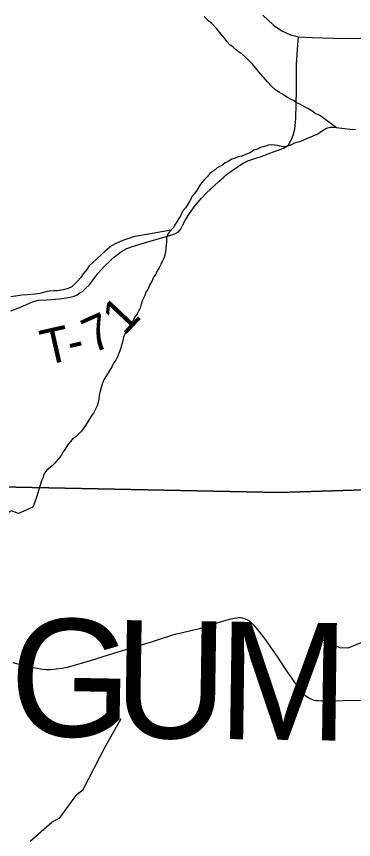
# Model space of a CAD drawing. Extents: x 0 to 34, y 0 to 22.
# Drawn here: x 27.33 to 27.873, y 17.319 to 18.646 of the extents above; entities that cross this region are included whole.
import ezdxf

# ---------------------------------------------------------------- set-up
doc = ezdxf.new("R2010")
doc.units = 0
for name, color, linetype in [('GM_X_Adjacent_County', 7, 'Continuous'), ('GM_X_Adjacent_County_Text', 7, 'Continuous'), ('GM_X_County', 7, 'Continuous'), ('GM_X_County_Road', 7, 'Continuous'), ('GM_X_Minor_River', 7, 'Continuous'), ('GM_X_Township', 7, 'Continuous'), ('GM_X_Township_Road', 7, 'Continuous'), ('GM_X_Township_Road_Text', 7, 'Continuous')]:
    doc.layers.add(name, color=color, linetype=linetype)

msp = doc.modelspace()

# ---------------------------------------------------------------- linework, layer by layer
at = {"layer": 'GM_X_Adjacent_County'}
for points in [[(29.1279, 17.8574), (28.6324, 17.8677), (28.1264, 17.8728), (27.8903, 17.8826), (27.7531, 17.8783), (27.1422, 17.8906), (26.9072, 17.9017), (26.4988, 17.9198), (26.3979, 17.9244), (26.2521, 17.9299)], [(26.2521, 17.9299), (26.3979, 17.9244), (26.4988, 17.9198), (26.9072, 17.9017), (27.1422, 17.8906), (27.7531, 17.8783), (27.8903, 17.8826), (28.1264, 17.8728), (28.6324, 17.8677), (29.1279, 17.8574)]]:
    msp.add_lwpolyline(points, dxfattribs=at)
at = {"layer": 'GM_X_County'}
for points in [[(26.2521, 17.9299), (26.3979, 17.9244), (26.4988, 17.9198), (26.9072, 17.9017), (27.1422, 17.8906), (27.7531, 17.8783), (27.8903, 17.8826), (28.1264, 17.8728), (28.6324, 17.8677), (29.1279, 17.8574)], [(29.1279, 17.8574), (28.6324, 17.8677), (28.1264, 17.8728), (27.8903, 17.8826), (27.7531, 17.8783), (27.1422, 17.8906), (26.9072, 17.9017), (26.4988, 17.9198), (26.3979, 17.9244), (26.2521, 17.9299)]]:
    msp.add_lwpolyline(points, dxfattribs=at)
at = {"layer": 'GM_X_County_Road'}
for points in [[(27.7267, 18.6482), (27.7441, 18.6319), (27.7571, 18.6229), (27.7713, 18.6162), (27.7839, 18.613)], [(27.7839, 18.613), (27.806, 18.6118), (27.8403, 18.6107), (27.8718, 18.6103), (27.8963, 18.6115)]]:
    msp.add_lwpolyline(points, dxfattribs=at)
at = {"layer": 'GM_X_Minor_River'}
for points in [[(27.8456, 18.4663), (27.82, 18.4853), (27.8163, 18.4872), (27.8109, 18.4895), (27.8071, 18.4925), (27.7992, 18.4978), (27.7912, 18.5019), (27.7855, 18.5053), (27.7817, 18.5068), (27.776, 18.5102), (27.7722, 18.5121), (27.7662, 18.5155), (27.7574, 18.5212), (27.7536, 18.5235), (27.7479, 18.5273), (27.7411, 18.5329), (27.7335, 18.5413), (27.7202, 18.5568), (27.7103, 18.5689), (27.7046, 18.5742), (27.6993, 18.5799), (27.6928, 18.5856), (27.6875, 18.589), (27.6837, 18.592), (27.6791, 18.5965), (27.6734, 18.6003), (27.6689, 18.6056), (27.6655, 18.6102), (27.659, 18.6177), (27.6525, 18.6261), (27.6445, 18.6344), (27.6396, 18.6382), (27.6324, 18.6461)], [(27.8758, 18.463), (27.8675, 18.4638), (27.8584, 18.4645), (27.8497, 18.466), (27.8406, 18.4668), (27.8349, 18.4667), (27.8292, 18.4652), (27.8228, 18.4614), (27.8152, 18.4561), (27.811, 18.4546), (27.8023, 18.4507), (27.7982, 18.4492), (27.7891, 18.445), (27.7777, 18.4416), (27.7713, 18.4382), (27.7634, 18.4355), (27.7592, 18.4359), (27.7543, 18.4366), (27.7505, 18.4377), (27.7455, 18.4385), (27.7399, 18.4388), (27.7357, 18.4385), (27.7293, 18.4362), (27.7228, 18.4346), (27.7183, 18.432), (27.7122, 18.4301), (27.7062, 18.4263), (27.7013, 18.4243), (27.6929, 18.4209), (27.6869, 18.4194), (27.6812, 18.4167), (27.6766, 18.4156), (27.671, 18.4121), (27.6661, 18.4099), (27.6615, 18.4061), (27.6532, 18.4019), (27.6479, 18.3973), (27.6419, 18.3939), (27.6381, 18.3882), (27.632, 18.3825), (27.6286, 18.3783), (27.6249, 18.3726), (27.6207, 18.3665), (27.6162, 18.3593), (27.6124, 18.3555), (27.6105, 18.3513), (27.6083, 18.3475), (27.6022, 18.3376), (27.5977, 18.3327), (27.5958, 18.3285), (27.5939, 18.3247), (27.5913, 18.3202), (27.5883, 18.3148), (27.5856, 18.3107), (27.583, 18.3057), (27.5758, 18.2981), (27.5728, 18.2932), (27.5717, 18.289), (27.5713, 18.2833), (27.571, 18.2765), (27.5706, 18.2727), (27.5699, 18.2666), (27.5676, 18.2575), (27.5646, 18.2511), (27.5623, 18.2461), (27.5593, 18.2397), (27.5563, 18.2359), (27.5541, 18.2302), (27.5507, 18.2256), (27.548, 18.2184), (27.5446, 18.2135)], [(27.5789, 18.3014), (27.5179, 18.2904), (27.5107, 18.2881), (27.5054, 18.2862), (27.4982, 18.2835), (27.4899, 18.2797), (27.4831, 18.2759), (27.4725, 18.2675), (27.4668, 18.2622), (27.46, 18.2558), (27.4517, 18.2482), (27.4468, 18.2436), (27.443, 18.2379), (27.4373, 18.231), (27.4332, 18.2253), (27.4283, 18.2189), (27.4245, 18.2151), (27.4188, 18.2098), (27.4128, 18.2071), (27.4052, 18.2052), (27.3957, 18.2036), (27.3901, 18.2036), (27.3829, 18.2029), (27.3791, 18.2025), (27.3749, 18.2013), (27.3673, 18.1994), (27.3601, 18.1979), (27.3473, 18.1971), (27.3386, 18.1963), (27.3317, 18.1955), (27.3208, 18.194)], [(27.5446, 18.2135), (27.5412, 18.2055), (27.5382, 18.2013), (27.5363, 18.196), (27.533, 18.1884), (27.5307, 18.1823), (27.5288, 18.1755), (27.5266, 18.1705), (27.5243, 18.1667), (27.5205, 18.1618), (27.5171, 18.1542), (27.5111, 18.1455), (27.5062, 18.1367), (27.5024, 18.1288), (27.4998, 18.1185), (27.4961, 18.1067), (27.4927, 18.0972), (27.4897, 18.0915), (27.4863, 18.087), (27.4833, 18.0809), (27.4791, 18.0741), (27.475, 18.0669), (27.4708, 18.0612), (27.4686, 18.0547), (27.4663, 18.0479), (27.4641, 18.0395), (27.4629, 18.0346), (27.4622, 18.0289), (27.4607, 18.022), (27.4596, 18.0183), (27.4577, 18.0137), (27.4539, 18.0065), (27.4501, 18.0012), (27.4468, 17.9962), (27.4437, 17.9909), (27.4392, 17.9841), (27.4343, 17.9772), (27.4264, 17.9692), (27.4196, 17.9639), (27.4135, 17.9567), (27.4075, 17.9476), (27.4049, 17.9438), (27.4022, 17.9388), (27.3916, 17.9255), (27.3871, 17.9213), (27.3788, 17.9145), (27.375, 17.9096), (27.3735, 17.9058), (27.372, 17.9016), (27.3701, 17.897), (27.365, 17.8814)], [(27.365, 17.8814), (27.3615, 17.8687), (27.3563, 17.8549), (27.3329, 17.8446), (27.3218, 17.8486), (27.314, 17.8445), (27.2886, 17.8365), (27.2621, 17.8368), (27.2489, 17.8269), (27.2403, 17.8151), (27.2119, 17.8104), (27.1896, 17.8046), (27.1772, 17.794)], [(28.1101, 17.8688), (28.1036, 17.8534), (28.073, 17.8298), (28.0477, 17.8088), (27.9937, 17.7753), (27.9718, 17.7562), (27.9605, 17.7437), (27.9441, 17.6875), (27.9382, 17.6616), (27.931, 17.6495), (27.9201, 17.6419), (27.8989, 17.6418), (27.8634, 17.6276), (27.8505, 17.6279), (27.8187, 17.643)], [(27.3518, 17.3162), (27.3865, 17.3467), (27.3998, 17.3536), (27.4268, 17.3916), (27.4374, 17.3996), (27.4648, 17.4528), (27.4716, 17.4661), (27.4982, 17.514)]]:
    msp.add_lwpolyline(points, dxfattribs=at)
at = {"layer": 'GM_X_Township'}
for points in [[(30.8167, 17.8174), (30.1304, 17.8301), (29.8296, 17.8449), (29.1279, 17.8574), (28.6324, 17.8677), (28.1264, 17.8728), (27.8903, 17.8826), (27.7531, 17.8783), (27.1422, 17.8906), (26.9072, 17.9017), (26.4988, 17.9198), (26.3979, 17.9244), (26.2521, 17.9299), (26.228, 17.2045)], [(26.2521, 17.9299), (26.3979, 17.9244), (26.4988, 17.9198), (26.9072, 17.9017), (27.1422, 17.8906), (27.7531, 17.8783), (27.8903, 17.8826), (28.1264, 17.8728), (28.6324, 17.8677), (29.1279, 17.8574)]]:
    msp.add_lwpolyline(points, dxfattribs=at)
at = {"layer": 'GM_X_Township_Road'}
for points in [[(27.3207, 18.1711), (27.3363, 18.1771), (27.3557, 18.186), (27.365, 18.1886), (27.3788, 18.1888), (27.3992, 18.1907), (27.4106, 18.1925), (27.4165, 18.1935), (27.4227, 18.195), (27.4275, 18.1969), (27.4317, 18.2002), (27.4359, 18.2027), (27.4416, 18.2079), (27.4473, 18.2133), (27.4543, 18.223), (27.4607, 18.2315), (27.4657, 18.2369), (27.4722, 18.2436), (27.4784, 18.2498), (27.4853, 18.2565), (27.4925, 18.2623), (27.4992, 18.2672), (27.5077, 18.2719), (27.5183, 18.2757), (27.5454, 18.2834), (27.5618, 18.2886), (27.5784, 18.2935), (27.5859, 18.296), (27.5906, 18.2985), (27.5938, 18.3022), (27.5973, 18.3087), (27.6025, 18.3189), (27.6087, 18.3283), (27.6179, 18.341), (27.6276, 18.3529), (27.6365, 18.3621), (27.6475, 18.3723), (27.6564, 18.3802), (27.6641, 18.3867), (27.6678, 18.3906), (27.6733, 18.3951), (27.6835, 18.4021), (27.6937, 18.4088), (27.7027, 18.413), (27.7105, 18.4157), (27.7239, 18.4204), (27.7463, 18.4289), (27.7604, 18.4336), (27.7678, 18.4392), (27.7724, 18.4465), (27.7756, 18.4544), (27.7784, 18.464), (27.78, 18.4814), (27.7808, 18.5271), (27.7812, 18.5693), (27.7831, 18.6), (27.7839, 18.613)], [(27.3237, 17.6043), (27.3417, 17.5996), (27.3568, 17.5961), (27.3659, 17.5944), (27.3721, 17.5937), (27.3783, 17.5932), (27.3845, 17.5932), (27.3938, 17.5938), (27.403, 17.5951), (27.4121, 17.5969), (27.4211, 17.5992), (27.4419, 17.6055), (27.4864, 17.6191), (27.5042, 17.6245), (27.531, 17.6326), (27.5487, 17.6382), (27.5635, 17.6429), (27.5783, 17.6476), (27.5872, 17.6502), (27.5932, 17.6517), (27.5992, 17.6531), (27.6109, 17.6557), (27.6224, 17.6585), (27.6283, 17.6602), (27.64, 17.6639), (27.6548, 17.6686), (27.6636, 17.6713), (27.6751, 17.6746), (27.6812, 17.6759), (27.6848, 17.6765), (27.6875, 17.6767), (27.6908, 17.6766), (27.6938, 17.6763), (27.6968, 17.6754), (27.6996, 17.6743), (27.7024, 17.673), (27.7049, 17.6713), (27.7073, 17.6693), (27.7117, 17.665), (27.7196, 17.6555), (27.7253, 17.6482), (27.7309, 17.6408), (27.7382, 17.6307), (27.7503, 17.6127), (27.7623, 17.5946), (27.7743, 17.5766), (27.7815, 17.5664), (27.7872, 17.5591), (27.7913, 17.5545), (27.7935, 17.5524), (27.7959, 17.5505), (27.7983, 17.5487), (27.801, 17.5471), (27.8038, 17.5457), (27.8066, 17.5446), (27.8096, 17.5437), (27.8126, 17.5431), (27.8157, 17.5427), (27.8219, 17.5424), (27.8312, 17.5422), (27.856, 17.5427), (27.8839, 17.5433)]]:
    msp.add_lwpolyline(points, dxfattribs=at)

# ---------------------------------------------------------------- texts
at = {"layer": 'GM_X_Adjacent_County_Text'}
for s, rotation, p in [('G', 358.9475, (27.3173, 17.4866)), ('U', 359.1434, (27.4855, 17.4835)), ('M', 359.1871, (27.6531, 17.481))]:
    msp.add_text(s, height=0.1894, rotation=rotation, dxfattribs=at).set_placement(p)
at = {"layer": 'GM_X_Township_Road_Text'}
for s, rotation, p in [('1', 46.7303, (27.5035, 18.1301)), ('7', 24.3671, (27.4521, 18.1017)), ('T', 12.7868, (27.376, 18.0831)), ('-', 13.0106, (27.4177, 18.0925))]:
    msp.add_text(s, height=0.0568, rotation=rotation, dxfattribs=at).set_placement(p)

doc.saveas('drawing.dxf')
